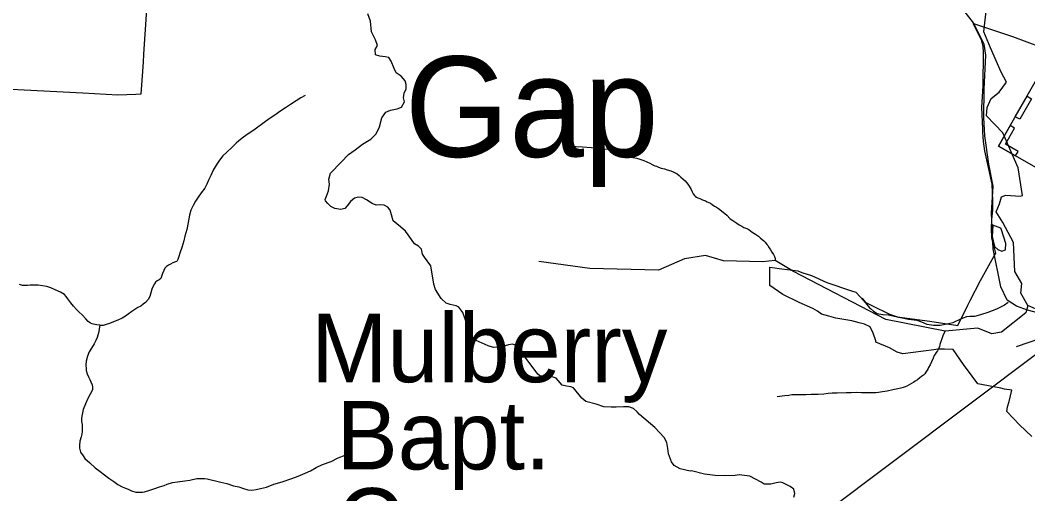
# Model space of a CAD drawing. Extents: x 1159738 to 1321356, y 736314 to 882035.
# Drawn here: x 1205885 to 1214710, y 834191 to 838340 of the extents above; entities that cross this region are included whole.
import ezdxf

# ---------------------------------------------------------------- set-up
doc = ezdxf.new("R2010")
doc.units = 0
for name, color, linetype in [('Exist Boundary Land Use Forest National US Forest Service', 7, 'Continuous'), ('Exist Cultural Cemetery CELL', 7, 'Continuous'), ('Exist Cultural Cemetery Label', 7, 'Continuous'), ('Exist Geographical Mountain Summit Label', 7, 'Continuous'), ('Exist Hydrographic Creek Single Shore', 7, 'Continuous'), ('Exist Hydrographic Misc Water Feature', 7, 'Continuous'), ('Exist Road Non-System Type 51', 7, 'Continuous'), ('Exist Road Secondary Structure Standard Bridge CELL', 7, 'Continuous'), ('Exist Road Secondary Structure Standard Bridge Number Label', 7, 'Continuous'), ('Exist Road Secondary Type 41 Attributed', 7, 'Continuous')]:
    doc.layers.add(name, color=color, linetype=linetype)

msp = doc.modelspace()

# ---------------------------------------------------------------- linework, layer by layer
at = {"layer": 'Exist Boundary Land Use Forest National US Forest Service'}
for points in [[(1205806.5, 837735.3), (1206433.5, 837702.2), (1206741.5, 837685.2), (1206898.5, 837692.2), (1206945.5, 837694.3), (1206948, 837730.8), (1206964.4, 837971.7), (1206969.2, 838040.9), (1206992.7, 838390), (1207008.5, 838623.3)], [(1213979.6, 835459.2), (1213929.7, 835458.3), (1213922.3, 835457.1), (1213885.7, 835451.2), (1213614.6, 835417.3), (1213566.6, 835430.3), (1213499.7, 835468.3), (1213378.6, 835519.3), (1213377.7, 835531.3), (1213355.6, 835598.3), (1213328.7, 835654.2), (1213279.6, 835678.2), (1213233.6, 835687.3), (1213169.6, 835705.2), (1213028.7, 835729.2), (1212966.6, 835746.3), (1212903.6, 835764.3), (1212866.7, 835789.3), (1212826.6, 835814.2), (1212708.7, 835867.2), (1212565.7, 835935.3), (1212449.6, 836014.3), (1212450.1, 836102.4), (1212450.6, 836176.3), (1212493.2, 836170), (1212532.6, 836164.3), (1212627.5, 836152.6), (1212695.7, 836144.3), (1212731.6, 836129.3), (1212816.6, 836102.2), (1212948.6, 836041.2), (1213165.6, 835969.3), (1213204.6, 835956.2), (1213245.7, 835913.1), (1213288.7, 835862.3), (1213324.7, 835819.3), (1213330.7, 835814.1), (1213358.6, 835790.2), (1213389.7, 835771.3), (1213435.9, 835762.7), (1213443.6, 835761.2), (1213489.6, 835758.3), (1213565.6, 835742.3), (1213850.6, 835704.3), (1214095.6, 835666.2), (1214184.8, 835842.4), (1214205.7, 835883.3), (1214295.6, 836058.3), (1214412.7, 836268.6), (1214428.7, 836297.3), (1214419.6, 836333.3), (1214412.7, 836361.4), (1214395.6, 836430.3), (1214390.6, 836516.3), (1214394.2, 836587.7), (1214394.6, 836594.3), (1214404.7, 836674.3), (1214402.6, 836756.3), (1214398.6, 836902.3), (1214334.6, 837196.3), (1214322.6, 837276.3), (1214315.7, 837362.3), (1214314.6, 837386.7), (1214306.6, 837575.3), (1214318.6, 837764.3), (1214321.6, 838058.3), (1214317.6, 838109.3), (1214306.3, 838157.7), (1214234.7, 838305.3), (1214234.7, 838309.3), (1214295, 838289.3), (1214357.6, 838268.6), (1214575.7, 838196.3), (1214952.7, 838057.3)], [(1214745.7, 834692.2), (1214635.7, 834795.2), (1214524.6, 834912.3), (1214531.6, 834952.2), (1214545.6, 834999.3), (1214569.6, 835097.3), (1214504.6, 835108.2), (1214472.6, 835117.3), (1214271.6, 835153.2), (1214223.6, 835222.2), (1214145.6, 835322.3), (1214055.7, 835455.2), (1213979.6, 835459.2)]]:
    msp.add_lwpolyline(points, dxfattribs=at)
at = {"layer": 'Exist Cultural Cemetery CELL'}
for points in [[(1214452.8, 837236.8), (1214848.5, 837927.8), (1215732.4, 837421.6), (1215336.6, 836730.6)], [(1214600.1, 837493.8), (1214703.1, 837673.7), (1214742.7, 837651.1), (1214639.6, 837471.2)], [(1214603.1, 837150.6), (1214625.7, 837190), (1214513.9, 837254), (1214594.6, 837394.8), (1214556, 837416.9), (1214452.8, 837236.8)]]:
    msp.add_lwpolyline(points, close=True, dxfattribs=at)
at = {"layer": 'Exist Hydrographic Creek Single Shore'}
msp.add_lwpolyline([(1214830.7, 835788.6), (1214710, 835840.6), (1214649.6, 835946.9), (1214657.9, 836032.3), (1214595.8, 836139.5), (1214584.5, 836392.2), (1214490.4, 836567.8), (1214432, 836659.3), (1214462.5, 836730.6), (1214480.3, 836791.6), (1214518.4, 836806.9), (1214643, 836796.7), (1214662.6, 836803.8), (1214625.3, 837045), (1214490.6, 837352.8), (1214348.2, 837502.9), (1214353.3, 837574.1), (1214388.9, 837653), (1214457.5, 837708.9), (1214523.6, 837795.4), (1214475.4, 837883.1), (1214383.8, 838096.8), (1214325.4, 838236.7), (1214369.6, 838628.2)], dxfattribs=at)
at = {"layer": 'Exist Hydrographic Misc Water Feature'}
for points in [[(1208380.6, 837679.6), (1208342, 837658.7), (1208303.4, 837633.7), (1208252.4, 837601.1), (1208209.6, 837572.1), (1208160.6, 837539.5), (1208124, 837514.5), (1208075, 837481.7), (1208034.3, 837450.9), (1207932.2, 837375.6), (1207883.3, 837344.8), (1207842.4, 837315.9), (1207799.5, 837283.1), (1207776.9, 837261.6), (1207739.9, 837224.6), (1207694.7, 837183.8), (1207659.9, 837150.8), (1207630.8, 837113.5), (1207601.5, 837068.3), (1207576.4, 837024.9), (1207555.1, 836979.4), (1207536, 836938), (1207519, 836902.4), (1207502.1, 836868.8), (1207471, 836827.7), (1207443.9, 836788.3), (1207421, 836755), (1207399.9, 836715.4), (1207380.8, 836674), (1207367.5, 836630.2), (1207355.8, 836566.6), (1207344.1, 836506.8), (1207326.6, 836447.3), (1207317.5, 836407.5), (1207299.9, 836347.9), (1207284.5, 836298.3), (1207275.6, 836268.5), (1207267, 836242.7), (1207256.5, 836227), (1207246.4, 836221.3), (1207222.2, 836213.9), (1207201.9, 836202.4), (1207183.7, 836193), (1207167.2, 836181.4), (1207152.9, 836167.7), (1207142.4, 836148.1), (1207131.7, 836120.3), (1207122.9, 836094.5), (1207116.4, 836076.7), (1207102, 836065.1), (1207085.7, 836055.5), (1207071.5, 836045.9), (1207061.1, 836030.2), (1207050.6, 836010.4), (1207039.8, 835982.7), (1207030.9, 835951), (1207020, 835919.2), (1207007.4, 835893.5), (1206982.7, 835866.2), (1206964.1, 835850.7), (1206943.7, 835835.2), (1206917.4, 835823.9), (1206899, 835810.4), (1206864.4, 835787.3), (1206831.8, 835764.2), (1206807.3, 835746.8), (1206778.8, 835729.5), (1206742.3, 835712.6), (1206703.9, 835697.6), (1206667.4, 835682.5), (1206639.1, 835673.3), (1206612.9, 835664), (1206588.9, 835664.7), (1206583, 835666.9)], [(1210702.1, 837234.5), (1210810.2, 837229.6), (1210890.1, 837223.4), (1210964, 837215.4), (1211037.8, 837209.4), (1211061.7, 837206.7), (1211077.6, 837202.3), (1211093.6, 837197.9), (1211121.2, 837187.1), (1211143.1, 837178.5), (1211164.8, 837169.9), (1211184.5, 837161.4), (1211214.4, 837152.6), (1211252, 837137.5), (1211285.8, 837130.6), (1211319.6, 837119.7), (1211347.3, 837109), (1211373, 837098.2), (1211400.6, 837085.5), (1211420.4, 837075), (1211442.2, 837064.3), (1211458.1, 837059.9), (1211475.8, 837051.4), (1211499.6, 837042.8), (1211529.4, 837036), (1211551.2, 837027.4), (1211585, 837018.5), (1211602.8, 837012), (1211622.6, 837003.4), (1211638.3, 836993), (1211655.9, 836978.5), (1211671.6, 836964.1), (1211691.2, 836947.6), (1211708.7, 836931), (1211720.4, 836918.7), (1211731.9, 836902.4), (1211743.5, 836884.1), (1211760.7, 836855.6), (1211770.3, 836835.3), (1211779.7, 836819), (1211791.4, 836804.7), (1211797.2, 836798.5), (1211809, 836788.2), (1211820.7, 836781.9), (1211836.7, 836777.5), (1211860.4, 836766.9), (1211886.1, 836756.1), (1211902, 836749.7), (1211915.7, 836741.3), (1211929.6, 836736.9), (1211945.4, 836724.5), (1211967, 836709.9), (1211982.7, 836701.5), (1212002.4, 836688.9), (1212057.2, 836645.4), (1212072.8, 836631), (1212104.1, 836600.1), (1212125.7, 836585.5), (1212143.3, 836573), (1212161, 836560.5), (1212180.8, 836548), (1212206.3, 836535.3), (1212222.1, 836524.8), (1212247.8, 836514.2), (1212267.6, 836505.7), (1212296.9, 836482.9), (1212326.5, 836464), (1212350.1, 836447.3), (1212369.6, 836430.8), (1212381.5, 836422.5), (1212398.9, 836406), (1212410.7, 836395.7), (1212424.3, 836375.3), (1212432, 836365.1), (1212445.5, 836346.7), (1212457, 836328.4), (1212468.4, 836308), (1212481.9, 836287.6), (1212491.3, 836269.4), (1212495.1, 836259.3), (1212496.9, 836251.2), (1212496.8, 836243.2), (1212496.4, 836235.2)], [(1214404.2, 836543.7), (1214398, 836445.8), (1214416.7, 836358.2), (1214447.9, 836331.2), (1214483.3, 836316.6), (1214514.6, 836329.1), (1214518.7, 836383.2), (1214479.2, 836502), (1214472.9, 836518.7), (1214404.2, 836543.7)], [(1214710, 835840.6), (1214692.7, 835775.7), (1214479.6, 835606.1), (1214395.6, 835591.3), (1214272.7, 835640.6), (1213984.7, 835616.5), (1213465.6, 835718.3), (1212659.1, 836137.3), (1212496.4, 836235.2), (1212386.6, 836222.4), (1212045.6, 836232.5), (1211887.5, 836278.3), (1211703.6, 836249.2), (1211475.6, 836148.7), (1210875.6, 836164), (1210427.6, 836225.5)], [(1206583, 835666.9), (1206557, 835671.6), (1206529.1, 835676.3), (1206515.3, 835678.7), (1206501.4, 835685), (1206479.8, 835699.7), (1206460.4, 835722.2), (1206427.3, 835757.1), (1206401.9, 835781.8), (1206378.5, 835804.5), (1206351.3, 835835.3), (1206330.1, 835863.8), (1206303.1, 835898.6), (1206287.5, 835919), (1206274, 835935.4), (1206238.7, 835958.4), (1206193.1, 835977.6), (1206155.5, 835994.6), (1206117.8, 836005.7), (1206080.1, 836012.7), (1206042, 836017.7), (1206006, 836018.7), (1205972, 836017.6), (1205950.1, 836016.2), (1205925.9, 836014.9), (1205905.9, 836015.4), (1205880.1, 836024.1)], [(1206583, 835666.9), (1206578.1, 835636.9), (1206573.4, 835609), (1206566.6, 835581.2), (1206560, 835559.4), (1206549.3, 835533.7), (1206534.6, 835504), (1206509.5, 835466.7), (1206490.6, 835433.2), (1206475.5, 835395.6), (1206464.4, 835353.8), (1206461.6, 835319.9), (1206462.5, 835285.9), (1206464.1, 835269.8), (1206471.4, 835241.5), (1206482.7, 835215.2), (1206496, 835190.9), (1206503.5, 835170.7), (1206516.8, 835144.3), (1206520.3, 835124.2), (1206519.5, 835100.2), (1206498.6, 835062.7), (1206479.5, 835025.1), (1206458.3, 834979.7), (1206437, 834930.3), (1206427.6, 834884.5), (1206422.8, 834852.6), (1206424, 834824.5), (1206427.3, 834796.5), (1206428.4, 834764.4), (1206427.6, 834736.4), (1206425.1, 834712.5), (1206420.4, 834688.5), (1206407.4, 834652.9), (1206404.5, 834614.9), (1206403.8, 834590.9), (1206414.8, 834556.6), (1206435.9, 834524), (1206453.3, 834501.5), (1206494.3, 834462.4), (1206543.2, 834419), (1206586.3, 834385.8), (1206662.8, 834327.7), (1206706.1, 834298.5), (1206741.5, 834273.6), (1206778.8, 834252.5), (1206806.6, 834239.8), (1206830.3, 834231.2), (1206861.9, 834218.3), (1206899.7, 834205.3), (1206929.7, 834204.5), (1206955.6, 834205.7), (1206975.8, 834209.2), (1207022.2, 834224), (1207064.7, 834238.8), (1207107.1, 834251.6), (1207145.4, 834262.7), (1207173.8, 834275.9), (1207218.2, 834288.7), (1207264.3, 834295.5), (1207326.6, 834303.8), (1207372.8, 834310.5), (1207431.4, 834325), (1207469.3, 834323.9), (1207499.3, 834325.1), (1207523.3, 834322.5), (1207557.1, 834313.6), (1207596.8, 834304.5), (1207642.6, 834293.2), (1207696.2, 834279.8), (1207753.8, 834262.1), (1207799.5, 834250.9), (1207841.1, 834237.8), (1207878.8, 834224.8), (1207914.9, 834221.8), (1207953.1, 834228.8), (1207991.4, 834237.7), (1208041.7, 834250.4), (1208106.3, 834274.7), (1208181, 834296.6), (1208265.8, 834326.4), (1208320.5, 834344.9), (1208381.2, 834371.3), (1208427.8, 834392), (1208478.6, 834422.6), (1208533.3, 834447.3), (1208608, 834473.2), (1208671, 834505.5), (1208731.7, 834527.9)], [(1213984.7, 835616.5), (1213969.8, 835582.9), (1213961.1, 835557.1), (1213944, 835517.6), (1213939.5, 835499.7), (1213935, 835479.8), (1213930.7, 835465.9), (1213924.2, 835454.1), (1213918, 835444.2), (1213907.6, 835428.5), (1213899.3, 835414.7), (1213890.9, 835400.9), (1213880.2, 835379.2), (1213867.4, 835347.5), (1213854.6, 835321.9), (1213840.1, 835298.2), (1213835.7, 835288.3), (1213827.4, 835274.6), (1213816.9, 835254.9), (1213806.5, 835243.1), (1213796.3, 835231.4), (1213779.9, 835217.8), (1213765.5, 835206.2), (1213745, 835188.7), (1213722.7, 835177.3), (1213710.6, 835169.7), (1213692.1, 835158.1), (1213671.8, 835144.7), (1213651.5, 835133.2), (1213635.3, 835127.7), (1213619.1, 835122.1), (1213599, 835116.6), (1213572.8, 835109.3), (1213528.5, 835100.5), (1213478.1, 835089.9), (1213436, 835085), (1213401.8, 835077.9), (1213377.8, 835076.6), (1213341.7, 835075.6), (1213299.6, 835074.7), (1213253.6, 835075.9), (1213209.6, 835077.1), (1213163.5, 835074.4), (1213119.5, 835075.6), (1213039.4, 835073.7), (1212995.3, 835073), (1212961.3, 835069.8), (1212923.2, 835064.9), (1212874.9, 835060.2), (1212812.8, 835059.9), (1212764.9, 835059.1), (1212728.8, 835058.2), (1212694.7, 835057.1), (1212668.8, 835057.7), (1212642.6, 835056.5), (1212616.5, 835051.2), (1212582.4, 835048.1), (1212514.1, 835040)]]:
    msp.add_lwpolyline(points, dxfattribs=at)
at = {"layer": 'Exist Road Non-System Type 51'}
for points in [[(1210308.9, 835387), (1210221.9, 835493.3), (1210198.3, 835500.7), (1210162.9, 835494.8), (1210095, 835475.6), (1210031.6, 835472.6), (1209984.4, 835487.4), (1209931.3, 835511), (1209877.8, 835533.4), (1209852.8, 835555.6), (1209818.9, 835604.3), (1209799.7, 835672.2), (1209762.8, 835779.9), (1209725.9, 835825.7), (1209702.3, 835837.5), (1209650.7, 835847.8), (1209616.8, 835859.6), (1209572.5, 835902.4), (1209523.9, 835980.6), (1209509.1, 836027.9), (1209481.1, 836187.3), (1209425.1, 836263.1), (1209408.9, 836291.1), (1209400.1, 836333.9), (1209375, 836359), (1209338.1, 836379.7), (1209313, 836419.6), (1209283.5, 836457.9), (1209259.9, 836490.4), (1209217.2, 836528.8), (1209150.8, 836580.4), (1209136, 836633.6), (1209127.2, 836676.4), (1209105.1, 836701.5), (1209074.1, 836717.7), (1209040.2, 836720.6), (1209001.8, 836719.2), (1208967.9, 836732.5), (1208917.8, 836766.4), (1208879.4, 836787.1), (1208847, 836788.5), (1208813, 836781.2), (1208777.6, 836751.6), (1208748.1, 836713.3), (1208729, 836691.1), (1208695, 836680.8), (1208640.5, 836689.7), (1208605.1, 836708.8), (1208578.5, 836732.5), (1208559.3, 836757.5), (1208557.1, 836770.1), (1208567.4, 836798.1), (1208586.6, 836845.4), (1208594, 836902.9), (1208589.5, 836947.2), (1208604.3, 836998.9), (1208697.2, 837094.8), (1208760.6, 837162.7), (1208817.8, 837203.3), (1208882.7, 837252), (1208957.9, 837297.8), (1209003.7, 837345), (1209033.2, 837404.1), (1209053.8, 837483.8), (1209087.7, 837532.5), (1209129, 837551.7), (1209188, 837562), (1209224.9, 837576.7), (1209250, 837624), (1209243.9, 837658.2), (1209249.8, 837699.6), (1209264.6, 837739.4), (1209264.6, 837774.8), (1209255.7, 837808.8), (1209223.3, 837848.6), (1209179, 837876.7), (1209159.9, 837915), (1209133.3, 837981.5), (1209112.7, 838012.5), (1209081.7, 838018.4), (1209036, 838024.3), (1208996.1, 838036.1), (1208993.2, 838081.8), (1209013.8, 838118.7), (1208996.1, 838166), (1208962.2, 838238.3), (1208953.4, 838331.3), (1208929.8, 838395.1)], [(1214538.2, 835865.3), (1214505.5, 835842.4), (1214435.8, 835807.5), (1214360.6, 835780.2), (1214295.2, 835757.3), (1214243.9, 835744.2), (1214201.4, 835743.1), (1214172, 835741), (1214127.3, 835723.5), (1214053.2, 835689.7), (1213999.8, 835676.6), (1213943.2, 835665.7), (1213883.2, 835665.7), (1213827.6, 835673.3), (1213782.9, 835695.2), (1213741.5, 835708.2), (1213663.7, 835717), (1213580.9, 835735.6), (1213502.4, 835760.7), (1213345.5, 835838.1), (1213295.4, 835863.2), (1213280.1, 835881.7), (1213261.6, 835904.6)], [(1212661.2, 834162.2), (1212668.5, 834193.2), (1212661.2, 834230.1), (1212627.2, 834255.2), (1212565.3, 834286.2), (1212541.7, 834293.6), (1212506.3, 834287.7), (1212459.1, 834275.8), (1212401.6, 834275.8), (1212373.6, 834292.1), (1212276.2, 834345.2), (1212181.8, 834357), (1212146.4, 834351.1), (1212062.3, 834349.6), (1211972.4, 834352.6), (1211879.5, 834361.5), (1211765.9, 834391), (1211754.1, 834389.5), (1211665.6, 834410.2), (1211611.7, 834437.4), (1211589.5, 834471.4), (1211563, 834540.8), (1211557.1, 834586.5), (1211549.7, 834639.6), (1211524.6, 834685.4), (1211443.5, 834772.5), (1211309.3, 834886.1), (1211290.1, 834909.7), (1211257.7, 834937.8), (1211216.4, 834952.6), (1211169.2, 834954), (1211105.8, 834951.1), (1211061.5, 834949.6), (1210996.6, 834952.6), (1210930.2, 834974.7), (1210839.9, 835000.3), (1210803, 835028.4), (1210730.7, 835118.4), (1210707.1, 835128.7), (1210668.8, 835133.2), (1210631.9, 835142), (1210580.3, 835202.5), (1210553.7, 835212.9), (1210491.8, 835215.8), (1210437.2, 835223.2), (1210419.5, 835238), (1210308.9, 835387)]]:
    msp.add_lwpolyline(points, dxfattribs=at)
at = {"layer": 'Exist Road Secondary Structure Standard Bridge CELL'}
msp.add_line((1214610.4, 835480), (1214824.1, 835554.6), dxfattribs=at)
at = {"layer": 'Exist Road Secondary Structure Standard Bridge Number Label'}
msp.add_line((1214836, 835453), (1211106.1, 832650.4), dxfattribs=at)
at = {"layer": 'Exist Road Secondary Type 41 Attributed'}
msp.add_lwpolyline([(1214805.9, 835772), (1214706, 835799.3), (1214612.1, 835835.6), (1214530.3, 835887.2), (1214472.7, 836002.4), (1214406.1, 836335.8), (1214391, 836648), (1214405.9, 836885.5), (1214369.6, 837079.5), (1214333.2, 837325), (1214324.1, 837485.6), (1214327.2, 837734.2), (1214342.3, 838032.3), (1214327.2, 838129.3), (1214233.3, 838317.3), (1214112.1, 838474.9)], dxfattribs=at)

# ---------------------------------------------------------------- texts
at = {"layer": 'Exist Cultural Cemetery Label'}
for s, p in [('Mulberry', (1208433.9, 835168.4)), (' Bapt.', (1208433.9, 834404.4)), (' Cem.', (1208433.9, 833640.4))]:
    msp.add_text(s, height=600, dxfattribs=at).set_placement(p)
at = {"layer": 'Exist Geographical Mountain Summit Label'}
msp.add_text(' Gap', height=880, dxfattribs=at).set_placement((1208926.6, 837142.2))

doc.saveas('drawing.dxf')
